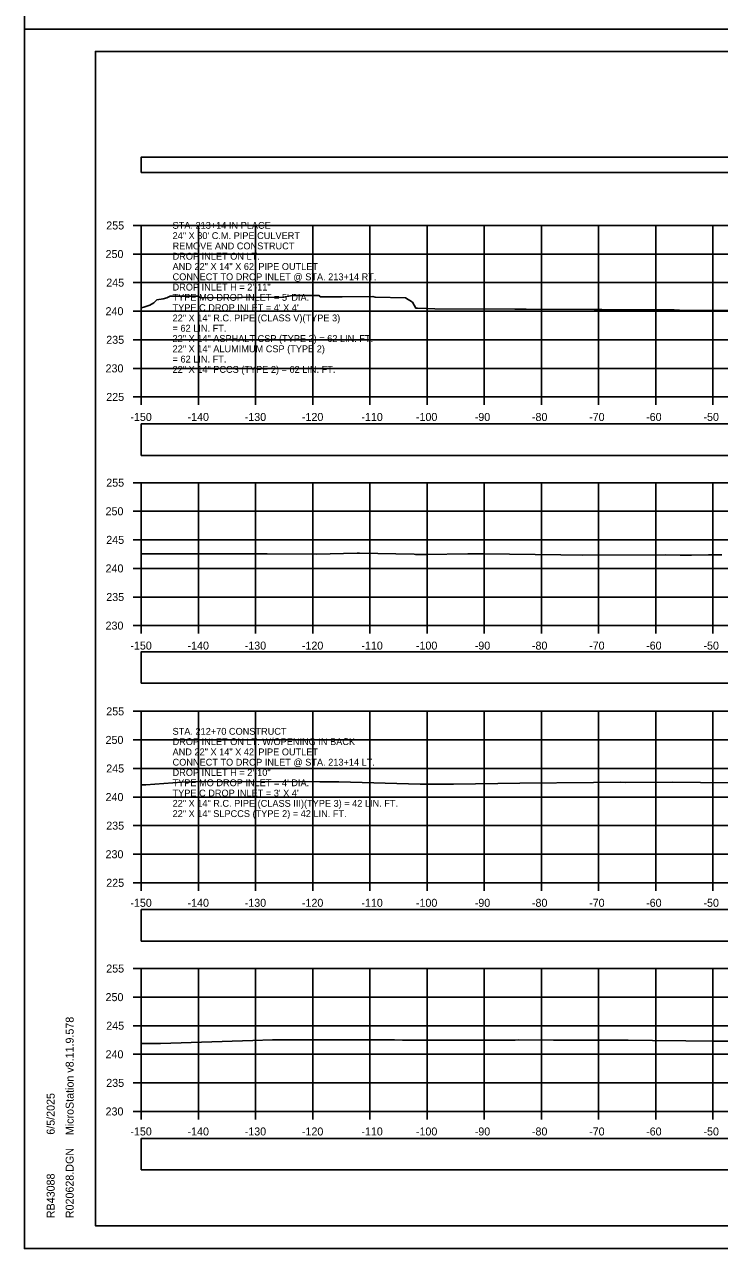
# Model space of a CAD drawing. Extents: x 1369627 to 1374022, y 380035 to 398173.
# Drawn here: x 1371928.1 to 1372049.7, y 382812.2 to 383026.3 of the extents above; entities that cross this region are included whole.
import ezdxf

# ---------------------------------------------------------------- set-up
doc = ezdxf.new("R2010")
doc.units = 0
for name, color, linetype in [('Default', 7, 'Continuous'), ('R_Axis', 7, 'Continuous'), ('R_Axis Annot', 7, 'Continuous'), ('R_Border', 7, 'Continuous'), ('R_Exist Surface', 7, 'Continuous'), ('R_Grid', 7, 'Continuous'), ('R_No Plot', 7, 'Continuous'), ('R_Water Annot', 7, 'Continuous')]:
    doc.layers.add(name, color=color, linetype=linetype)

msp = doc.modelspace()

# ---------------------------------------------------------------- linework, layer by layer
at = {"layer": 'Default'}
for points in [[(1371948.53, 383000.41), (1372248.53, 383000.41), (1372248.53, 383003.12), (1371948.53, 383003.12)], [(1371948.53, 382950.92), (1372248.53, 382950.92), (1372248.53, 382956.44), (1371948.53, 382956.44)], [(1371948.53, 382911.05), (1372248.53, 382911.05), (1372248.53, 382916.57), (1371948.53, 382916.57)], [(1371948.53, 382865.94), (1372248.53, 382865.94), (1372248.53, 382871.46), (1371948.53, 382871.46)], [(1371948.53, 382825.91), (1372248.53, 382825.91), (1372248.53, 382831.43), (1371948.53, 382831.43)]]:
    msp.add_lwpolyline(points, close=True, dxfattribs=at)
at = {"layer": 'R_Axis'}
for p, q in [((1371947.13, 382991.15), (1371948.53, 382991.15)), ((1371948.53, 382961.15), (1371948.53, 382991.15)), ((1371947.13, 382986.15), (1371948.53, 382986.15)), ((1371947.13, 382981.15), (1371948.53, 382981.15)), ((1371947.13, 382976.15), (1371948.53, 382976.15)), ((1371947.13, 382971.15), (1371948.53, 382971.15)), ((1371947.13, 382966.15), (1371948.53, 382966.15)), ((1371947.13, 382961.15), (1371948.53, 382961.15)), ((1371948.53, 382961.15), (1372248.53, 382961.15)), ((1371948.53, 382959.75), (1371948.53, 382961.15)), ((1371958.53, 382959.75), (1371958.53, 382961.15)), ((1371968.53, 382959.75), (1371968.53, 382961.15)), ((1371978.53, 382959.75), (1371978.53, 382961.15)), ((1371988.53, 382959.75), (1371988.53, 382961.15)), ((1371998.53, 382959.75), (1371998.53, 382961.15)), ((1372008.53, 382959.75), (1372008.53, 382961.15)), ((1372018.53, 382959.75), (1372018.53, 382961.15)), ((1372028.53, 382959.75), (1372028.53, 382961.15)), ((1372038.53, 382959.75), (1372038.53, 382961.15)), ((1372048.53, 382959.75), (1372048.53, 382961.15)), ((1371947.13, 382946.15), (1371948.53, 382946.15)), ((1371948.53, 382921.15), (1371948.53, 382946.15)), ((1371947.13, 382941.15), (1371948.53, 382941.15)), ((1371947.13, 382936.15), (1371948.53, 382936.15)), ((1371947.13, 382931.15), (1371948.53, 382931.15)), ((1371947.13, 382926.15), (1371948.53, 382926.15)), ((1371947.13, 382921.15), (1371948.53, 382921.15)), ((1371948.53, 382921.15), (1372248.53, 382921.15)), ((1371948.53, 382919.75), (1371948.53, 382921.15)), ((1371958.53, 382919.75), (1371958.53, 382921.15)), ((1371968.53, 382919.75), (1371968.53, 382921.15)), ((1371978.53, 382919.75), (1371978.53, 382921.15)), ((1371988.53, 382919.75), (1371988.53, 382921.15)), ((1371998.53, 382919.75), (1371998.53, 382921.15)), ((1372008.53, 382919.75), (1372008.53, 382921.15)), ((1372018.53, 382919.75), (1372018.53, 382921.15)), ((1372028.53, 382919.75), (1372028.53, 382921.15)), ((1372038.53, 382919.75), (1372038.53, 382921.15)), ((1372048.53, 382919.75), (1372048.53, 382921.15)), ((1371947.13, 382906.15), (1371948.53, 382906.15)), ((1371948.53, 382876.15), (1371948.53, 382906.15)), ((1371947.13, 382901.15), (1371948.53, 382901.15)), ((1371947.13, 382896.15), (1371948.53, 382896.15)), ((1371947.13, 382891.15), (1371948.53, 382891.15)), ((1371947.13, 382886.15), (1371948.53, 382886.15)), ((1371947.13, 382881.15), (1371948.53, 382881.15)), ((1371947.13, 382876.15), (1371948.53, 382876.15)), ((1371948.53, 382876.15), (1372248.53, 382876.15)), ((1371948.53, 382874.75), (1371948.53, 382876.15)), ((1371958.53, 382874.75), (1371958.53, 382876.15)), ((1371968.53, 382874.75), (1371968.53, 382876.15)), ((1371978.53, 382874.75), (1371978.53, 382876.15)), ((1371988.53, 382874.75), (1371988.53, 382876.15)), ((1371998.53, 382874.75), (1371998.53, 382876.15)), ((1372008.53, 382874.75), (1372008.53, 382876.15)), ((1372018.53, 382874.75), (1372018.53, 382876.15)), ((1372028.53, 382874.75), (1372028.53, 382876.15)), ((1372038.53, 382874.75), (1372038.53, 382876.15)), ((1372048.53, 382874.75), (1372048.53, 382876.15)), ((1371947.13, 382861.15), (1371948.53, 382861.15)), ((1371948.53, 382836.15), (1371948.53, 382861.15)), ((1371947.13, 382856.15), (1371948.53, 382856.15)), ((1371947.13, 382851.15), (1371948.53, 382851.15)), ((1371947.13, 382846.15), (1371948.53, 382846.15)), ((1371947.13, 382841.15), (1371948.53, 382841.15)), ((1371947.13, 382836.15), (1371948.53, 382836.15)), ((1371948.53, 382836.15), (1372248.53, 382836.15)), ((1371948.53, 382834.75), (1371948.53, 382836.15)), ((1371958.53, 382834.75), (1371958.53, 382836.15)), ((1371968.53, 382834.75), (1371968.53, 382836.15)), ((1371978.53, 382834.75), (1371978.53, 382836.15)), ((1371988.53, 382834.75), (1371988.53, 382836.15)), ((1371998.53, 382834.75), (1371998.53, 382836.15)), ((1372008.53, 382834.75), (1372008.53, 382836.15)), ((1372018.53, 382834.75), (1372018.53, 382836.15)), ((1372028.53, 382834.75), (1372028.53, 382836.15)), ((1372038.53, 382834.75), (1372038.53, 382836.15)), ((1372048.53, 382834.75), (1372048.53, 382836.15))]:
    msp.add_line(p, q, dxfattribs=at)
at = {"layer": 'R_Border'}
for p, q in [((1371940.53, 383021.61), (1372256.71, 383021.61)), ((1371940.53, 382816.15), (1371940.53, 383021.61)), ((1371940.53, 382816.15), (1371940.53, 382816.15)), ((1372256.71, 382816.15), (1371940.53, 382816.15))]:
    msp.add_line(p, q, dxfattribs=at)
at = {"layer": 'R_Exist Surface'}
for points in [[(1371948.53, 382976.75), (1371948.6, 382976.75), (1371948.99, 382976.87), (1371950.04, 382977.2), (1371950.75, 382977.6), (1371951.29, 382978.16), (1371952.35, 382978.29), (1371953.03, 382978.48), (1371953.61, 382978.79), (1371957.95, 382978.78), (1371958.44, 382978.8), (1371959, 382978.52), (1371973.45, 382978.58), (1371974.67, 382978.87), (1371975.3, 382978.9), (1371979.67, 382978.89), (1371979.68, 382978.89), (1371979.85, 382978.67), (1371983.7, 382978.68), (1371989.06, 382978.7), (1371989.48, 382978.62), (1371994.73, 382978.52), (1371995.97, 382977.75), (1371996.56, 382976.71), (1371996.88, 382976.68), (1371999.91, 382976.58), (1372013.88, 382976.49), (1372015.87, 382976.48), (1372027.78, 382976.43), (1372029.11, 382976.43), (1372041.77, 382976.37), (1372042.66, 382976.36), (1372051.99, 382976.3)], [(1371948.53, 382933.68), (1371948.83, 382933.69), (1371955.31, 382933.7), (1371970.54, 382933.71), (1371979.22, 382933.67), (1371986.29, 382933.81), (1371986.37, 382933.81), (1371986.42, 382933.81), (1371986.49, 382933.81), (1371986.69, 382933.8), (1371996.28, 382933.63), (1371996.5, 382933.59), (1371996.96, 382933.61), (1371998.37, 382933.6), (1372005.68, 382933.7), (1372008.44, 382933.68), (1372021.9, 382933.53), (1372025.65, 382933.49), (1372040.16, 382933.52), (1372042.82, 382933.46), (1372044.76, 382933.49), (1372047.73, 382933.52), (1372050.1, 382933.54)], [(1371948.53, 382893.29), (1371949.36, 382893.29), (1371955.62, 382893.73), (1371958.71, 382893.87), (1371979.77, 382893.79), (1371983.07, 382893.79), (1371997.32, 382893.38), (1372003.18, 382893.38), (1372014.73, 382893.58), (1372027.65, 382893.68), (1372032.44, 382893.76), (1372033.26, 382893.71), (1372041.52, 382893.75), (1372046.37, 382893.72), (1372056.86, 382893.66)], [(1371948.53, 382848.06), (1371949.75, 382848.04), (1371951.02, 382848.04), (1371951.05, 382848.03), (1371951.92, 382848.04), (1371968.07, 382848.54), (1371971.47, 382848.69), (1371974.8, 382848.68), (1371992.83, 382848.67), (1371994.22, 382848.63), (1372013.61, 382848.65), (1372013.92, 382848.65), (1372014.51, 382848.66), (1372020.66, 382848.65), (1372033, 382848.65), (1372033.72, 382848.64), (1372037.96, 382848.59), (1372043.81, 382848.5), (1372048.68, 382848.45), (1372059.42, 382848.42)]]:
    msp.add_lwpolyline(points, dxfattribs=at)
at = {"layer": 'R_Grid'}
for p, q in [((1371948.53, 382991.15), (1372248.53, 382991.15)), ((1371948.53, 382961.15), (1371948.53, 382991.15)), ((1371958.53, 382961.15), (1371958.53, 382991.15)), ((1371968.53, 382961.15), (1371968.53, 382991.15)), ((1371978.53, 382961.15), (1371978.53, 382991.15)), ((1371988.53, 382961.15), (1371988.53, 382991.15)), ((1371998.53, 382961.15), (1371998.53, 382991.15)), ((1372008.53, 382961.15), (1372008.53, 382991.15)), ((1372018.53, 382961.15), (1372018.53, 382991.15)), ((1372028.53, 382961.15), (1372028.53, 382991.15)), ((1372038.53, 382961.15), (1372038.53, 382991.15)), ((1372048.53, 382961.15), (1372048.53, 382991.15)), ((1371948.53, 382986.15), (1372248.53, 382986.15)), ((1371948.53, 382981.15), (1372248.53, 382981.15)), ((1371948.53, 382976.15), (1372248.53, 382976.15)), ((1371948.53, 382971.15), (1372248.53, 382971.15)), ((1371948.53, 382966.15), (1372248.53, 382966.15)), ((1371948.53, 382961.15), (1372248.53, 382961.15)), ((1371948.53, 382946.15), (1372248.53, 382946.15)), ((1371948.53, 382921.15), (1371948.53, 382946.15)), ((1371958.53, 382921.15), (1371958.53, 382946.15)), ((1371968.53, 382921.15), (1371968.53, 382946.15)), ((1371978.53, 382921.15), (1371978.53, 382946.15)), ((1371988.53, 382921.15), (1371988.53, 382946.15)), ((1371998.53, 382921.15), (1371998.53, 382946.15)), ((1372008.53, 382921.15), (1372008.53, 382946.15)), ((1372018.53, 382921.15), (1372018.53, 382946.15)), ((1372028.53, 382921.15), (1372028.53, 382946.15)), ((1372038.53, 382921.15), (1372038.53, 382946.15)), ((1372048.53, 382921.15), (1372048.53, 382946.15)), ((1371948.53, 382941.15), (1372248.53, 382941.15)), ((1371948.53, 382936.15), (1372248.53, 382936.15)), ((1371948.53, 382931.15), (1372248.53, 382931.15)), ((1371948.53, 382926.15), (1372248.53, 382926.15)), ((1371948.53, 382921.15), (1372248.53, 382921.15)), ((1371948.53, 382906.15), (1372248.53, 382906.15)), ((1371948.53, 382876.15), (1371948.53, 382906.15)), ((1371958.53, 382876.15), (1371958.53, 382906.15)), ((1371968.53, 382876.15), (1371968.53, 382906.15)), ((1371978.53, 382876.15), (1371978.53, 382906.15)), ((1371988.53, 382876.15), (1371988.53, 382906.15)), ((1371998.53, 382876.15), (1371998.53, 382906.15)), ((1372008.53, 382876.15), (1372008.53, 382906.15)), ((1372018.53, 382876.15), (1372018.53, 382906.15)), ((1372028.53, 382876.15), (1372028.53, 382906.15)), ((1372038.53, 382876.15), (1372038.53, 382906.15)), ((1372048.53, 382876.15), (1372048.53, 382906.15)), ((1371948.53, 382901.15), (1372248.53, 382901.15)), ((1371948.53, 382896.15), (1372248.53, 382896.15)), ((1371948.53, 382891.15), (1372248.53, 382891.15)), ((1371948.53, 382886.15), (1372248.53, 382886.15)), ((1371948.53, 382881.15), (1372248.53, 382881.15)), ((1371948.53, 382876.15), (1372248.53, 382876.15)), ((1371948.53, 382861.15), (1372248.53, 382861.15)), ((1371948.53, 382836.15), (1371948.53, 382861.15)), ((1371958.53, 382836.15), (1371958.53, 382861.15)), ((1371968.53, 382836.15), (1371968.53, 382861.15)), ((1371978.53, 382836.15), (1371978.53, 382861.15)), ((1371988.53, 382836.15), (1371988.53, 382861.15)), ((1371998.53, 382836.15), (1371998.53, 382861.15)), ((1372008.53, 382836.15), (1372008.53, 382861.15)), ((1372018.53, 382836.15), (1372018.53, 382861.15)), ((1372028.53, 382836.15), (1372028.53, 382861.15)), ((1372038.53, 382836.15), (1372038.53, 382861.15)), ((1372048.53, 382836.15), (1372048.53, 382861.15)), ((1371948.53, 382856.15), (1372248.53, 382856.15)), ((1371948.53, 382851.15), (1372248.53, 382851.15)), ((1371948.53, 382846.15), (1372248.53, 382846.15)), ((1371948.53, 382841.15), (1372248.53, 382841.15)), ((1371948.53, 382836.15), (1372248.53, 382836.15))]:
    msp.add_line(p, q, dxfattribs=at)
at = {"layer": 'R_No Plot'}
for p, q in [((1371928.13, 383025.51), (1372261.46, 383025.51)), ((1371928.13, 383025.51), (1372261.46, 383025.51)), ((1371928.13, 382812.17), (1372261.46, 382812.17))]:
    msp.add_line(p, q, dxfattribs=at)
for points in [[(1371928.12, 383238.84), (1372261.46, 383238.84), (1372261.46, 383025.5), (1371928.12, 383025.5)], [(1371928.12, 383025.51), (1372261.46, 383025.51), (1372261.46, 382812.17), (1371928.12, 382812.17)], [(1372174.45, 383021.61), (1372194.07, 383021.61), (1372194.07, 383011.73), (1372210.18, 383011.73), (1372233.38, 383011.73), (1372233.38, 382979.06), (1372256.59, 382979.06), (1372256.71, 382816.15), (1371940.53, 382816.15), (1371940.53, 383021.61)]]:
    msp.add_lwpolyline(points, close=True, dxfattribs=at)

# ---------------------------------------------------------------- texts
at = {"layer": 'R_Axis Annot'}
for s, p in [('255', (1371942.42, 382990.45)), ('250', (1371942.3, 382985.45)), ('245', (1371942.42, 382980.45)), ('240', (1371942.3, 382975.45)), ('235', (1371942.42, 382970.45)), ('230', (1371942.3, 382965.45)), ('225', (1371942.42, 382960.45)), ('-150', (1371946.64, 382956.95)), ('-140', (1371956.64, 382956.95)), ('-130', (1371966.64, 382956.95)), ('-120', (1371976.64, 382956.95)), ('-110', (1371987.04, 382956.95)), ('-100', (1371996.58, 382956.95)), ('-90', (1372006.87, 382956.95)), ('-80', (1372016.87, 382956.95)), ('-70', (1372026.87, 382956.95)), ('-60', (1372036.84, 382956.95)), ('-50', (1372046.87, 382956.95)), ('255', (1371942.42, 382945.45)), ('250', (1371942.3, 382940.45)), ('245', (1371942.42, 382935.45)), ('240', (1371942.3, 382930.45)), ('235', (1371942.42, 382925.45)), ('230', (1371942.3, 382920.45)), ('-150', (1371946.64, 382916.95)), ('-140', (1371956.64, 382916.95)), ('-130', (1371966.64, 382916.95)), ('-120', (1371976.64, 382916.95)), ('-110', (1371987.04, 382916.95)), ('-100', (1371996.58, 382916.95)), ('-90', (1372006.87, 382916.95)), ('-80', (1372016.87, 382916.95)), ('-70', (1372026.87, 382916.95)), ('-60', (1372036.84, 382916.95)), ('-50', (1372046.87, 382916.95)), ('255', (1371942.42, 382905.45)), ('250', (1371942.3, 382900.45)), ('245', (1371942.42, 382895.45)), ('240', (1371942.3, 382890.45)), ('235', (1371942.42, 382885.45)), ('230', (1371942.3, 382880.45)), ('225', (1371942.42, 382875.45)), ('-150', (1371946.64, 382871.95)), ('-140', (1371956.64, 382871.95)), ('-130', (1371966.64, 382871.95)), ('-120', (1371976.64, 382871.95)), ('-110', (1371987.04, 382871.95)), ('-100', (1371996.58, 382871.95)), ('-90', (1372006.87, 382871.95)), ('-80', (1372016.87, 382871.95)), ('-70', (1372026.87, 382871.95)), ('-60', (1372036.84, 382871.95)), ('-50', (1372046.87, 382871.95)), ('255', (1371942.42, 382860.45)), ('250', (1371942.3, 382855.45)), ('245', (1371942.42, 382850.45)), ('240', (1371942.3, 382845.45)), ('235', (1371942.42, 382840.45)), ('230', (1371942.3, 382835.45)), ('-150', (1371946.64, 382831.95)), ('-140', (1371956.64, 382831.95)), ('-130', (1371966.64, 382831.95)), ('-120', (1371976.64, 382831.95)), ('-110', (1371987.04, 382831.95)), ('-100', (1371996.58, 382831.95)), ('-90', (1372006.87, 382831.95)), ('-80', (1372016.87, 382831.95)), ('-70', (1372026.87, 382831.95)), ('-60', (1372036.84, 382831.95)), ('-50', (1372046.87, 382831.95))]:
    msp.add_text(s, height=1.4, dxfattribs=at).set_placement(p)
at = {"layer": 'R_Border'}
for s, p in [('MicroStation v8.11.9.578', (1371936.72, 382832.01)), ('6/5/2025', (1371933.4, 382832.08)), ('R020628.DGN', (1371936.72, 382817.48)), ('RB43088', (1371933.4, 382817.48))]:
    msp.add_text(s, height=1.4, rotation=90, dxfattribs=at).set_placement(p)
at = {"layer": 'R_Water Annot'}
for s, p in [('STA. 213+14 IN PLACE', (1371954.02, 382990.57)), ('24" X 30\' C.M. PIPE CULVERT', (1371954.02, 382988.77)), ('REMOVE AND CONSTRUCT', (1371954.02, 382986.97)), ('DROP INLET ON LT.', (1371954.02, 382985.17)), ('AND 22" X 14" X 62\' PIPE OUTLET', (1371954.02, 382983.37)), ('CONNECT TO DROP INLET @ STA. 213+14 RT.', (1371954.02, 382981.57)), ('DROP INLET H = 2\'-11"', (1371954.02, 382979.77)), ("TYPE MO DROP INLET = 5' DIA.", (1371954.02, 382977.97)), ("TYPE C DROP INLET = 4' X 4'", (1371954.02, 382976.17)), ('22" X 14" R.C. PIPE (CLASS V)(TYPE 3)', (1371954.02, 382974.37)), ('= 62 LIN. FT.', (1371954.02, 382972.57)), ('22" X 14" ASPHALT CSP (TYPE 2) = 62 LIN. FT.', (1371954.02, 382970.77)), ('22" X 14" ALUMIMUM CSP (TYPE 2)', (1371954.02, 382968.97)), ('= 62 LIN. FT.', (1371954.02, 382967.17)), ('22" X 14" PCCS (TYPE 2) = 62 LIN. FT.', (1371954.02, 382965.37)), ('STA. 212+70 CONSTRUCT', (1371954.02, 382902.05)), ('DROP INLET ON LT. W/OPENING IN BACK', (1371954.02, 382900.25)), ('AND 22" X 14" X 42\' PIPE OUTLET', (1371954.02, 382898.45)), ('CONNECT TO DROP INLET @ STA. 213+14 LT.', (1371954.02, 382896.65)), ('DROP INLET H = 2\'-10"', (1371954.02, 382894.85)), ("TYPE MO DROP INLET = 4' DIA.", (1371954.02, 382893.05)), ("TYPE C DROP INLET = 3' X 4'", (1371954.02, 382891.25)), ('22" X 14" R.C. PIPE (CLASS III)(TYPE 3) = 42 LIN. FT.', (1371954.02, 382889.45)), ('22" X 14" SLPCCS (TYPE 2) = 42 LIN. FT.', (1371954.02, 382887.65))]:
    msp.add_text(s, height=1.2, dxfattribs=at).set_placement(p)

doc.saveas('drawing.dxf')
